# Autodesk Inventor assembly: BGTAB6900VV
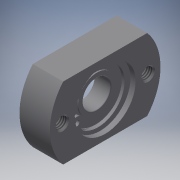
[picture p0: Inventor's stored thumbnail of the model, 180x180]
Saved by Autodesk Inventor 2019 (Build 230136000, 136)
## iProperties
Category: PARTsolutions
Company: MISUMI
Created: 2022-11
Part Number: BGTAB6900VV
Catalog Web Link: www.cadenas.de
Description: BGTAB, BGTCA, SBGTA-Bearings with Housings - Space Saving, Small Flange - Retained
Vendor: MISUMI
Document SubType Name: Assembly
Designer: psAdmin
Manufacturer: MISUMI
Mass: 8.03384 g
Surface Area: 53.5072 cm^2
Volume: 8.03384 cm^3
Density: 1 g/cm^3
Title: BGTAB6900VV
Author: Cadenas PARTsolutions
Comments: Bearings with Housings - Space Saving, Small Flange - Retained
PSOL_IDENT_0: {$CADENAS_DATA/23d-libs/misumi/metric/12_bearing_holders/bgtab_asmtab.prj},206 {VTYP=3D},{STYP=ASSTA
PSOL_IDENT_1: B},{NB=BGTAB6900VV},{LINA=BGTAB6900VV},{NN=BGTAB, BGTCA, SBGTA},{DATE=30.06.2021 12:58:21},{GEOMDATE=
PSOL_IDENT_2: 10.07.2015 02:10:34},{VERSION=},{LINEID=90},{WBVAR=MATB,ST,SEAL,ALT1},{WBNUMERIC=}  {NB=BGTAB6900VV}
PSOL_IDENT_3: ,{LINA=BGTAB6900VV},{KT=DUMMY},{PN=BGTAB6900VV},{TYPE=BGTAB},{MATB=S},{MATBALG= 'S' , 'Steel' , 'SS'
PSOL_IDENT_4: , 'Stainless Steel' },{ST=BO},{STALG= 'BO' , 'Black Oxide' , 'ENP' , 'Electroless Nickel Plating' }
PSOL_IDENT_5: ,{BN=6900},{SEAL=VV},{SEALALG= 'ZZ' , 'Double Shielded' , 'VV' , 'Non-Contact Sealed Rubber Seal' , '
PSOL_IDENT_6: DD' , 'Contact Sealed Rubber Seal' },{DD=10},{D=22},{B=6},{H=40},{W=26},{T=11},{DDHH=19},{A=31},{F=0
PSOL_IDENT_7: },{M=M5},{ALT1=},{M3D=5},{MM=1.15},{BDD2=23},{PPATH=bgtab/bgtab_asmtpl.prj}
NB: BGTAB6900VV
NN: BGTAB, BGTCA, SBGTA
NT: Bearings with Housings - Space Saving, Small Flange - Retained
NBSYN: $PN.
LINA: BGTAB6900VV
CATALOG: Misumi
PN: BGTAB6900VV
MATB: Steel
ST: Black Oxide
BN: 6900
SEAL: Non-Contact Sealed Rubber Seal
DD: 10
D: 22
B: 6
H: 40
W: 26
T: 11
DDHH: 19
A: 31
F: 0
M: M5
ALT1: Bearing and Retaining Ring Assembled
SUPPLIER: MISUMI
ARTICLENO: BGTAB6900VV
BOMINFO: BGTAB6900VV
CREATOR: CADENAS GmbH
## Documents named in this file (4)
- e:\temp\worker_COMMON_3\temp\tmp_6416_56_fsEaO\format_0\BGTAB6900VV.iam
- e:\temp\worker_COMMON_3\temp\tmp_6416_56_fsEaO\format_0\BGTAB6900VV_h.ipt
- e:\temp\worker_COMMON_3\temp\tmp_6416_56_fsEaO\format_0\bearing_6900.ipt
- e:\temp\worker_COMMON_3\temp\tmp_6416_56_fsEaO\format_0\RRING-C-INT-22.ipt
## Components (3 placed, 3 different names)
1. BGTAB6900VV_h:1 — to_bearings_XY@1 <-> to_housing_XY@2, to_bearings_Z@1 <-> to_housing_Z@2, to_bearings_YZ@1 <-> to_housing_YZ@2, bgcab_to_rring_XY@1 <-> rr_XY@3, bgcab_to_rring_Z@1 <-> rr_Z@3, bgcab_to_rring_YZ@1 <-> rr_YZ@3
2. bearing_6900:1 — to_bearings_XY@1 <-> to_housing_XY@2, to_bearings_Z@1 <-> to_housing_Z@2, to_bearings_YZ@1 <-> to_housing_YZ@2
3. RRING-C-INT-22:1 — bgcab_to_rring_XY@1 <-> rr_XY@3, bgcab_to_rring_Z@1 <-> rr_Z@3, bgcab_to_rring_YZ@1 <-> rr_YZ@3
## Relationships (6: Mate 4, Angle 2)
- to_bearings_XY@1 <-> to_housing_XY@2 [Mate]: BGTAB6900VV_h:1 ↔ bearing_6900:1
- to_bearings_Z@1 <-> to_housing_Z@2 [Mate]: BGTAB6900VV_h:1 ↔ bearing_6900:1
- to_bearings_YZ@1 <-> to_housing_YZ@2 [Angle]: BGTAB6900VV_h:1 ↔ bearing_6900:1
- bgcab_to_rring_XY@1 <-> rr_XY@3 [Mate]: BGTAB6900VV_h:1 ↔ RRING-C-INT-22:1
- bgcab_to_rring_Z@1 <-> rr_Z@3 [Mate]: BGTAB6900VV_h:1 ↔ RRING-C-INT-22:1
- bgcab_to_rring_YZ@1 <-> rr_YZ@3 [Angle]: BGTAB6900VV_h:1 ↔ RRING-C-INT-22:1
